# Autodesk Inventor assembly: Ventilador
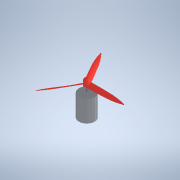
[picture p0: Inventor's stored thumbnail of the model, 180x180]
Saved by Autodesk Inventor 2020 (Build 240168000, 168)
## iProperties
Created: 2021-04
Part Number: Ventilador
Document SubType Name: Assembly
Designer: Sergio
Author: Sergio
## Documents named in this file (3)
- C:\Users\Sergio\Desktop\Modelo\Inventor\Ventilador.iam
- C:\Users\Sergio\Desktop\Modelo\Inventor\Motor.ipt
- C:\Users\Sergio\Desktop\Modelo\Inventor\Helice.ipt
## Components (2 placed, 2 different names)
1. Motor:1 — De rotación:1
2. Helice:2 — De rotación:1
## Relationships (1: RevoluteJoint 1)
- De rotación:1 [RevoluteJoint]: Motor:1 ↔ Helice:2
